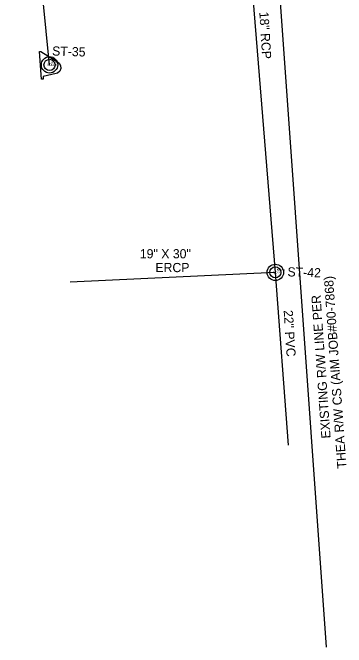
# Model space of a CAD drawing. Extents: x 509744 to 512285, y 1314862 to 1316822.
# Drawn here: x 511204.4 to 511306.3, y 1315033.6 to 1315227.3 of the extents above; entities that cross this region are included whole.
import ezdxf

# ---------------------------------------------------------------- set-up
doc = ezdxf.new("R2010")
doc.units = 0
for name, color, linetype in [('InletCurb_ep', 7, 'Continuous'), ('ManholeSW_ep', 7, 'Continuous'), ('NonPlottingEle_dp', 7, 'Continuous'), ('PipeCulvert_ep', 7, 'Continuous'), ('RWLine_ep', 7, 'Continuous'), ('TextElevLabel', 7, 'Continuous'), ('TextNotes', 7, 'Continuous'), ('TextPtLabel', 7, 'Continuous')]:
    doc.layers.add(name, color=color, linetype=linetype)

msp = doc.modelspace()

# ---------------------------------------------------------------- linework, layer by layer
at = {"layer": 'InletCurb_ep'}
for points in [[(511217.75, 1315208.69), (511213.74, 1315207.8), (511213.76, 1315207.01), (511213.28, 1315206.97), (511212.65, 1315215.46), (511213.01, 1315215.49)], [(511213.01, 1315215.49), (511217.31, 1315212.83), (511217.9, 1315212.43)], [(511217.9, 1315212.43), (511218.63, 1315211.93), (511219.08, 1315211.17), (511219.14, 1315210.29), (511218.82, 1315209.46), (511218.17, 1315208.87), (511217.75, 1315208.69)]]:
    msp.add_lwpolyline(points, dxfattribs=at)
at = {"layer": 'ManholeSW_ep'}
for centre, radius in [((511215.69, 1315211.37), 2.5), ((511215.69, 1315211.37), 1.7), ((511284.61, 1315148.04), 2.5), ((511284.61, 1315148.04), 1.7)]:
    msp.add_circle(centre, radius, dxfattribs=at)
at = {"layer": 'PipeCulvert_ep'}
for p, q in [((511267.16, 1315359.89), (511284.6, 1315148.05)), ((511215.67, 1315211.38), (511204.45, 1315326.14)), ((511284.6, 1315148.05), (511222.02, 1315145.06)), ((511284.6, 1315148.05), (511288.49, 1315095.34))]:
    msp.add_line(p, q, dxfattribs=at)
at = {"layer": 'RWLine_ep'}
msp.add_line((511300.26, 1315033.61), (511282.86, 1315277.33), dxfattribs=at)

# ---------------------------------------------------------------- texts
at = {"layer": 'ManholeSW_ep'}
for p in [(511215.01, 1315211.02), (511283.94, 1315147.69)]:
    msp.add_text('SD', height=0.7, dxfattribs=at).set_placement(p)
at = {"layer": 'NonPlottingEle_dp'}
for s, rotation, p in [('18" RCP', 273.588, (511279.71, 1315227.49)), ('ST-35', 358.1578, (511216.44, 1315214.23)), ('19" X 30"', 359.9807, (511243.25, 1315152.33)), ('ERCP', 359.9807, (511248, 1315148.12)), ('ST-42', 358.1578, (511288.28, 1315146.83)), ('22" PVC', 273.588, (511287.15, 1315136.44))]:
    msp.add_text(s, height=2.8, rotation=rotation, dxfattribs=at).set_placement(p)
at = {"layer": 'TextElevLabel'}
for s, p in [('14.86', (511216.17, 1315211.13)), ('13.53', (511285.1, 1315147.8))]:
    msp.add_text(s, height=0.5, dxfattribs=at).set_placement(p)
at = {"layer": 'TextNotes'}
for s, p in [('THEA R/W CS (AIM JOB#00-7868)', (511306.34, 1315088.28)), ('EXISTING R/W LINE PER', (511301.48, 1315097.45))]:
    msp.add_text(s, height=2.8, rotation=94.0425, dxfattribs=at).set_placement(p)
at = {"layer": 'TextPtLabel'}
for s, p in [('BN_601', (511216.17, 1315211.88)), ('BN_231', (511285.1, 1315148.55))]:
    msp.add_text(s, height=0.5, dxfattribs=at).set_placement(p)

doc.saveas('drawing.dxf')
